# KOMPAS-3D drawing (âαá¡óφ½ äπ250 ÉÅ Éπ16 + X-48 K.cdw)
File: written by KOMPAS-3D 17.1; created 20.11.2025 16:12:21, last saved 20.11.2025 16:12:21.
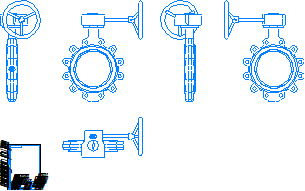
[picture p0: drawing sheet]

Sheet 1: A4, portrait

Title block, sheet 1: material: Сталь 20  ГОСТ 1050-2013; mass: 43,43; sheets: 1; sheet format: A4

Views: Вид 1, Спереди, Проекционный вид 2, Проекционный вид 3, Проекционный вид 4, Проекционный вид 5
Referenced files in \\adlc.lan\data\АДЛ_ПКД\3D-модели\ADL production\Дисковые поворотные затворы ГРАНВЭЛ\с резьбовыми проушинами с китайским редуктором Ру 16\KOMPAS 3D\: Гранвэл Ду250 РП Ру16 + X-48 K.m3d
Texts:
  Andrey
  АДЛ
Dimensions and other numbers on the sheet: 1:1; 1; 43,43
